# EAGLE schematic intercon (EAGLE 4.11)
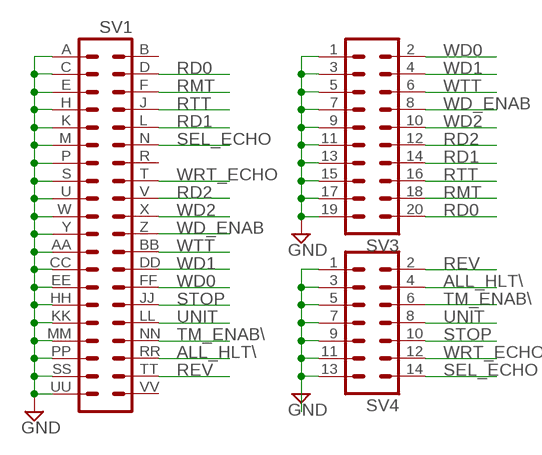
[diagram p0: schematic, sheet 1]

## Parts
SV1  DEC40PIN  [DEC40PIN]
SV3  MA10-2  [MA10-2]
SV4  MA07-2  [MA07-2]

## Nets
ALL_HLT\: SV1.RR SV4.4
GND: SV1.A SV1.AA SV1.C SV1.CC SV1.E SV1.EE SV1.H SV1.HH SV1.K SV1.KK SV1.M SV1.MM SV1.P SV1.PP SV1.S SV1.SS SV1.U SV1.UU SV1.W SV1.Y SV3.1 SV3.3 SV3.5 SV3.7 SV3.9 SV3.11 SV3.13 SV3.15 SV3.17 SV3.19 SV4.1 SV4.3 SV4.5 SV4.7 SV4.9 SV4.11 SV4.13
RD0: SV1.D SV3.20
RD1: SV1.L SV3.14
RD2: SV1.V SV3.12
REV: SV1.TT SV4.2
RMT: SV1.F SV3.18
RTT: SV1.J SV3.16
SEL_ECHO: SV1.N SV4.14
STOP: SV1.JJ SV4.10
TM_ENAB\: SV1.NN SV4.6
UNIT: SV1.LL SV4.8
WD0: SV1.FF SV3.2
WD1: SV1.DD SV3.4
WD2: SV1.X SV3.10
WD_ENAB: SV1.Z SV3.8
WRT_ECHO: SV1.T SV4.12
WTT: SV1.BB SV3.6
Unconnected: SV1.B SV1.R SV1.VV

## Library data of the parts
SV1 = dec-con:DEC40PIN: PIN HEADER
SV3 = con-lstb:MA10-2: PIN HEADER
SV4 = con-lstb:MA07-2: PIN HEADER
